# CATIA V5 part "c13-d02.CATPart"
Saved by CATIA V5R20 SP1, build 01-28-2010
Part number: Part1
Bounding box of the stored display mesh (mm): x -33 to 33, y -200.819 to 48, z -35 to 35
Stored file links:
  D:\v5_r20\psrt_files_downloaded\c13-catia-v5r20-prt\c13-catia-v5r20-figr13-10\c13-d02.CATPart
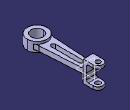
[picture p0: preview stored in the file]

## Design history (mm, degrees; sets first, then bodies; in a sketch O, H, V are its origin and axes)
Body1 (main body)
  Sketch1 on yz-plane, origin (0, 0, 0), H (0, 1, 0), V (0, 0, 1)
    line L1 (0, 0) -> (0, -35)
    point P1 (0, -35)
    line L2 (0, -35) -> (48, -35)
    point P2 (48, -35)
    line L3 (48, -35) -> (48, -25)
    point P3 (48, -25)
    line L4 (48, -25) -> (10, -25)
    point P4 (10, -25)
    line L5 (10, -25) -> (10, 0)
    point P5 (10, 0)
    point P6 (0, 0)
    point P7 (0, 0)
    point P8 (0, 35)
    point P9 (48, 35)
    point P10 (48, 25)
    point P11 (10, 25)
    point P12 (10, 0)
    point P13 (0, 0)
    line L6 (0, 0) -> (0, 35)
    line L7 (0, 35) -> (48, 35)
    line L8 (48, 35) -> (48, 25)
    line L9 (48, 25) -> (10, 25)
    line L10 (10, 25) -> (10, 0)
    length L8 = 10
    distance P3 L9 = 50
    length L2 = 48
    distance L10 L6 = 10
    vertical: L1 V, L3 V, L5 V
    horizontal: L2 H, L4 H
    symmetry: O P7 H, P1 P8 H, P2 P9 H, P3 P10 H, P4 P11 H, P5 P12 H, P6 P13 H, L1 L6 H, L2 L7 H, L3 L8 H, L4 L9 H, L5 L10 H
    coincidence: P13 P7, P12 P5, P6 P7
  Pad1: profile Sketch1, direction (1, 0, 0), length 16, mirrored extent
  Sketch2 on xy-plane, origin (0, 0, 0), H (1, 0, 0), V (0, 1, 0)
    circle A1 centre (0, -168) radius 33
    point P1 (0, -168)
    circle A2 centre (0, -168) radius 20
    distance P1 H = 168
    radius A1 = 33
    radius A2 = 20
    coincidence: P1 V
  Pad2: profile Sketch2, direction (0, 0, 1), length 16, mirrored extent
  Sketch3 on xy-plane, origin (0, 0, 0), H (1, 0, 0), V (0, 1, 0)
    line L1 (-16, 0) -> (-25, -146.4593)
    point P1 (-16, 0)
    point P2 (-25, -146.4593)
    line L2 (16, 0) -> (25, -146.4593)
    point P3 (16, 0)
    point P4 (25, -146.4593)
    reference projected line E1 (16, 48) -> (16, 0) from edge [face of Pad1 | face of Pad1]
    reference projected line E2 (-16, 48) -> (-16, 0) from edge [face of Pad1 | face of Pad1]
    projected circle E3 centre (0, -168) radius 33 from edge [face of Pad2 | face of Pad2]
    projected arc E4 centre (0, -168) radius 33 from (25, -146.4593) to (-25, -146.4593) ccw from edge [face of Pad2 | face of Pad2]
    line L3 (-16, 0) -> (16, 0)
    distance P4 P2 H = 50
    coincidence: P1 H, P3 H, P3 E1, P1 E2, P2 E3, P4 E3
    symmetry: P4 P2 V
    horizontal: L3 H
  Pad3: profile Sketch3, direction (0, 0, 1), length 8, mirrored extent
  Fillet1: radius 6, on edge [face of Pad1 | face of Pad3]; edge [face of Pad3 | face of Pad1]; edge [face of Pad1 | face of Pad1] (x2)
  Fillet2: radius 30, on edge [face of Pad3 | face of Pad2]; edge [face of Pad2 | face of Pad3]
  TritangentFillet1: Face1 face of Pad1, RemoveFace face of Pad1, Face2 face of Pad1
  TritangentFillet2: Face1 face of Pad1, RemoveFace face of Pad1, Face2 face of Pad1
  Sketch4 on face of Pad1, origin (2.8418, 32, 35), H (1, 0, 0), V (0, 1, 0)
    point P1 (-2.8418, 0)
    reference projected arc E1 centre (-2.8418, 0) radius 16 from (13.1582, 0) to (-18.8418, 0) ccw from edge [face of Pad1 | face of TritangentFillet1]
    concentricity: P1 E1
  Hole1: placed by Sketch4, at (0, 32, 35) direction (0, 0, -1), diameter 16, through (limit type 3)
  Sketch5 on face of Pad3, origin (0, 0, 8), H (1, 0, 0), V (0, 1, 0)
    construction line L1 (0, -25) -> (0, -115)
    point P1 (0, -25)
    line L2 (7, -25) -> (7, -115)
    line L3 (-7, -115) -> (-7, -25)
    arc A1 centre (0, -115) radius 7 from (7, -115) to (-7, -115) cw
    arc A2 centre (0, -25) radius 7 from (-7, -25) to (7, -25) cw
    distance P1 H = 25
    length L1 = 90
    radius A1 = 7
    coincidence: P1 V
    vertical: L1 V
    tangency: A1 L2, A2 L2, A1 L3, A2 L3
    parallelism: L1 L2
  Pocket1: profile Sketch5, direction (0, 0, -1), through (limit type 3)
